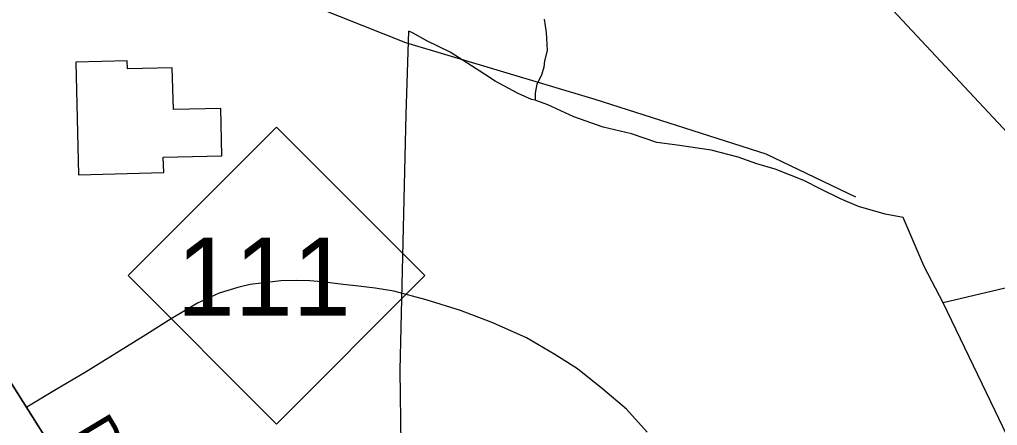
# Model space of a CAD drawing. Extents: x 2260773 to 2342389, y 552869 to 618546.
# Drawn here: x 2315983 to 2318179, y 596509 to 597420 of the extents above; entities that cross this region are included whole.
import ezdxf

# ---------------------------------------------------------------- set-up
doc = ezdxf.new("R2010")
doc.units = 0
for name, color, linetype in [('Exist Cultural Manufacturing Building Footprint', 7, 'Continuous'), ('Exist Hydrographic Misc Water Feature', 7, 'Continuous'), ('Exist Road Non-System Type 51', 7, 'Continuous'), ('Exist Road Primary NC Shield CELL', 7, 'Continuous'), ('Exist Road Primary NC Shield Number Label', 7, 'Continuous'), ('Exist Road Primary US Service Attributed', 7, 'Continuous'), ('Exist Road Secondary Type 51 Label', 7, 'Continuous'), ('Exist Utilities Electrical Transmission Line', 7, 'Continuous')]:
    doc.layers.add(name, color=color, linetype=linetype)

msp = doc.modelspace()

# ---------------------------------------------------------------- linework, layer by layer
at = {"layer": 'Exist Cultural Manufacturing Building Footprint'}
for p, q in [((2316224.7, 597326.7), (2316109.5, 597323.9)), ((2316109.5, 597323.9), (2316115.6, 597071.6)), ((2316225.1, 597309.2), (2316224.7, 597326.7)), ((2316326.1, 597311.6), (2316225.1, 597309.2)), ((2316328.4, 597217.6), (2316326.1, 597311.6)), ((2316435, 597220.2), (2316328.4, 597217.6)), ((2316437.6, 597114), (2316435, 597220.2)), ((2316305.9, 597110.8), (2316437.6, 597114)), ((2316306.8, 597076.2), (2316305.9, 597110.8)), ((2316115.6, 597071.6), (2316306.8, 597076.2))]:
    msp.add_line(p, q, dxfattribs=at)
at = {"layer": 'Exist Hydrographic Misc Water Feature'}
for points in [[(2317861.2, 597021.1), (2317660.2, 597118), (2317276.2, 597240.2), (2316850.3, 597367.4), (2316356.3, 597564.1), (2316038.3, 597708.7), (2315488.3, 597778.3), (2315378.2, 597846.1), (2315193.2, 598015.8), (2314991.3, 598257.1), (2314898.2, 598397.7), (2314746.2, 598578.6), (2314612.1, 598678.2), (2314253.3, 598765.4), (2314019.1, 598762.5), (2313355.2, 598581.4), (2312061.1, 598082.8), (2311970.2, 598065.9)], [(2317161.3, 597420.5), (2317165.8, 597390.6), (2317168.1, 597350.5), (2317162, 597326.7), (2317160.5, 597312.7), (2317155, 597294.5), (2317144.7, 597274.5), (2317141.4, 597254.4), (2317141.4, 597238.5)], [(2316839.6, 596459.6), (2316839.8, 596465.6), (2316838, 596633.4), (2316851.7, 597207.1), (2316857.7, 597393.2)], [(2317141.4, 597238.5), (2317133, 597240.2), (2317103.1, 597254), (2317051.2, 597281.3), (2317027, 597297.1), (2316950.1, 597346.4), (2316897.8, 597371.7), (2316865.7, 597389.6), (2316857.7, 597393.2)], [(2317968, 596975.5), (2317927.6, 596983.2), (2317867.5, 597000.3), (2317827.1, 597017.8), (2317783.1, 597039.4), (2317744.7, 597058.9), (2317680.5, 597084.4), (2317638.7, 597096), (2317596.7, 597111.3), (2317536.4, 597126.8), (2317460.3, 597137.8), (2317414.2, 597143.6), (2317357.8, 597163), (2317293.6, 597178), (2317227.8, 597201.2), (2317169.5, 597228.6), (2317141.4, 597238.5)], [(2318057.8, 596784.3), (2318014.8, 596865.8), (2317968, 596975.5)], [(2318400.7, 596868.2), (2318398.8, 596872.1), (2318209.4, 596819.9), (2318057.8, 596784.3)], [(2318448.7, 596127), (2318366, 596182), (2318337.7, 596201.6), (2318174.3, 596541.7), (2318057.8, 596784.3)]]:
    msp.add_lwpolyline(points, dxfattribs=at)
at = {"layer": 'Exist Road Non-System Type 51'}
msp.add_lwpolyline([(2317393, 596494), (2317346.2, 596545.7), (2317293, 596590.9), (2317236.5, 596636.1), (2317184.9, 596668.4), (2317121.9, 596705.5), (2317046.1, 596739.4), (2316973.5, 596766.9), (2316896, 596791.1), (2316823.4, 596810.5), (2316781.7, 596817.1), (2316744.4, 596821.8), (2316709.7, 596825.7), (2316662.2, 596831.5), (2316634.9, 596833.9), (2316604.5, 596834.2), (2316570.1, 596833.6), (2316525.5, 596828.1), (2316500.8, 596825.3), (2316473.3, 596818.5), (2316431.3, 596805.6), (2316382.6, 596783.4), (2316323.5, 596748.3), (2316260.3, 596708.8), (2316132.8, 596629.6), (2316061.8, 596587.7), (2315999.2, 596550.4)], dxfattribs=at)
at = {"layer": 'Exist Road Primary NC Shield CELL'}
msp.add_lwpolyline([(2316227, 596845.4), (2316560, 597178.4), (2316893, 596845.4), (2316560, 596512.4)], close=True, dxfattribs=at)
at = {"layer": 'Exist Road Primary US Service Attributed'}
msp.add_lwpolyline([(2315207.7, 597418.6), (2315309.7, 597328.9), (2315562.5, 597094.6), (2315636.8, 597017.8), (2315756, 596885.2), (2315867.5, 596746.5), (2315964.9, 596603.6), (2316208, 596217.3), (2315964.9, 596603.6), (2316208, 596217.3), (2316426.9, 595881.1), (2316496, 595756.6), (2316554.9, 595673.9), (2316655.5, 595505.1), (2316660.4, 595488.6), (2316659.6, 595468.8), (2316647.8, 595431.9), (2316628.3, 595389.7)], dxfattribs=at)
at = {"layer": 'Exist Utilities Electrical Transmission Line'}
msp.add_lwpolyline([(2317200.8, 598235.4), (2317419.2, 598002.6), (2319264.7, 596030.6)], dxfattribs=at)

# ---------------------------------------------------------------- texts
at = {"layer": 'Exist Road Primary NC Shield Number Label'}
msp.add_text('111', height=175, dxfattribs=at).set_placement((2316336.1, 596755.6))
at = {"layer": 'Exist Road Secondary Type 51 Label'}
msp.add_text('Dr.', height=95, rotation=300.9246, dxfattribs=at).set_placement((2316098.3, 596494.8))

doc.saveas('drawing.dxf')
